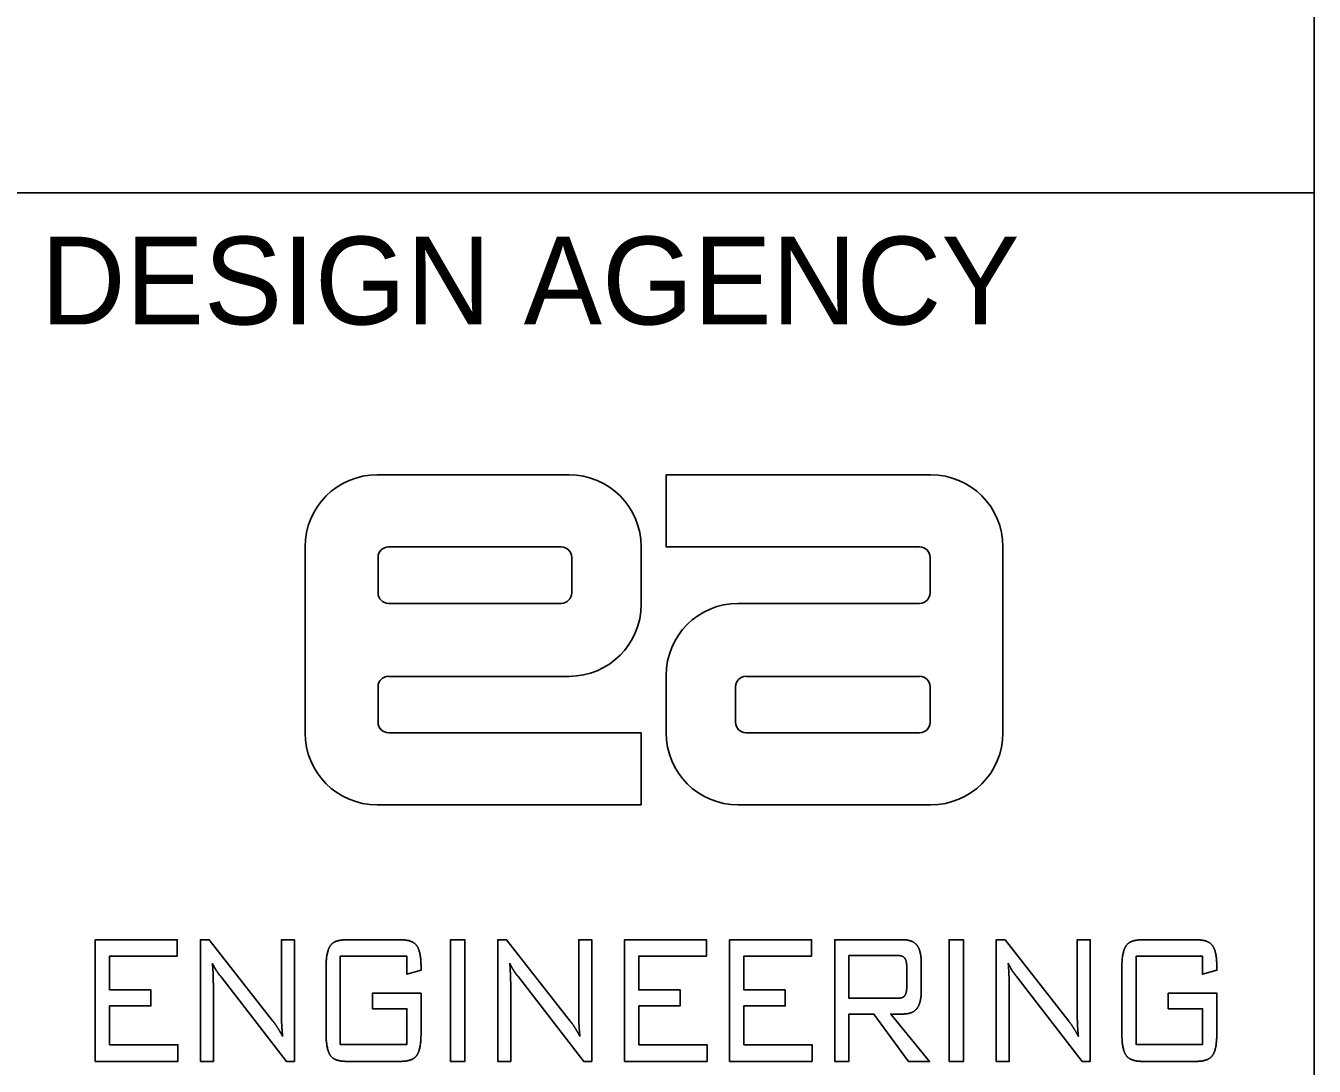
# Model space of a CAD drawing. Extents: x -18.5 to 46, y -14.2 to 42.5.
# Drawn here: x 32.033 to 33.5, y 3.506 to 4.69 of the extents above; entities that cross this region are included whole.
import ezdxf

# ---------------------------------------------------------------- set-up
doc = ezdxf.new("R2010")
doc.units = 0
for name, color, linetype in [('SH_Border', 7, 'Continuous'), ('SH_Data', 7, 'Continuous'), ('TX_X_20', 7, 'Continuous')]:
    doc.layers.add(name, color=color, linetype=linetype)

msp = doc.modelspace()

# ---------------------------------------------------------------- linework, layer by layer
at = {"layer": 'SH_Border'}
msp.add_line((32, 4.5), (33.5, 4.5), dxfattribs=at)
msp.add_lwpolyline([(1.5, 21.5), (33.5, 21.5), (33.5, 0.5), (1.5, 0.5)], close=True, dxfattribs=at)
at = {"layer": 'TX_X_20'}
for p, q in [((32.6515, 4.1788), (32.433, 4.1788)), ((32.433, 4.1788), (32.6515, 4.1788)), ((32.762, 4.1788), (33.0635, 4.1788)), ((32.762, 4.0967), (32.762, 4.1788)), ((32.351, 4.0967), (32.351, 3.8852)), ((32.351, 3.8852), (32.351, 4.0967)), ((32.4459, 4.0967), (32.6426, 4.0967)), ((32.6426, 4.0967), (32.4459, 4.0967)), ((32.7336, 4.0315), (32.7336, 4.0967)), ((32.7336, 4.0967), (32.7336, 4.0315)), ((33.0507, 4.0967), (32.762, 4.0967)), ((33.1456, 3.8852), (33.1456, 4.0967)), ((33.1456, 4.0967), (33.1456, 3.8852)), ((32.434, 4.0444), (32.434, 4.0849)), ((32.434, 4.0849), (32.434, 4.0444)), ((32.6545, 4.0849), (32.6545, 4.0444)), ((32.6545, 4.0444), (32.6545, 4.0849)), ((33.0626, 4.0849), (33.0626, 4.0444)), ((33.0626, 4.0444), (33.0626, 4.0849)), ((32.6426, 4.0325), (32.4459, 4.0325)), ((32.4459, 4.0325), (32.6426, 4.0325)), ((33.0507, 4.0325), (32.8441, 4.0325)), ((32.8441, 4.0325), (33.0507, 4.0325)), ((32.4459, 3.9494), (32.6515, 3.9494)), ((32.6515, 3.9494), (32.4459, 3.9494)), ((32.762, 3.9504), (32.762, 3.8852)), ((32.762, 3.8852), (32.762, 3.9504)), ((32.853, 3.9494), (33.0507, 3.9494)), ((33.0507, 3.9494), (32.853, 3.9494)), ((32.434, 3.8971), (32.434, 3.9376)), ((32.434, 3.9376), (32.434, 3.8971)), ((32.8411, 3.8971), (32.8411, 3.9376)), ((32.8411, 3.9376), (32.8411, 3.8971)), ((33.0626, 3.9376), (33.0626, 3.8971)), ((33.0626, 3.8971), (33.0626, 3.9376)), ((32.4459, 3.8852), (32.7336, 3.8852)), ((32.7336, 3.8852), (32.7336, 3.8031)), ((33.0507, 3.8852), (32.853, 3.8852)), ((32.853, 3.8852), (33.0507, 3.8852)), ((32.7336, 3.8031), (32.433, 3.8031)), ((32.8441, 3.8031), (33.0635, 3.8031)), ((33.0635, 3.8031), (32.8441, 3.8031)), ((32.3975, 3.6495), (32.4602, 3.6495)), ((33.3037, 3.6495), (33.3663, 3.6495)), ((32.3748, 3.5439), (32.3748, 3.6168)), ((33.0361, 3.6173), (33.0361, 3.5971)), ((33.0526, 3.5917), (33.0526, 3.6227)), ((33.2809, 3.5439), (33.2809, 3.6168)), ((32.4602, 3.5111), (32.3975, 3.5111)), ((33.3663, 3.5111), (33.3037, 3.5111))]:
    msp.add_line(p, q, dxfattribs=at)
for points in [[(33.0635, 4.1788), (32.762, 4.1788), (32.762, 4.0967), (33.0507, 4.0967)], [(32.433, 3.8031), (32.7336, 3.8031), (32.7336, 3.8852), (32.4459, 3.8852)], [(32.2465, 3.5927), (32.2465, 3.5111), (32.2317, 3.5111), (32.2317, 3.6495), (32.2419, 3.6495), (32.3144, 3.5569)], [(32.3239, 3.5736), (32.3239, 3.6495), (32.3387, 3.6495), (32.3387, 3.5111), (32.3297, 3.5111), (32.2553, 3.6074)], [(32.5851, 3.5927), (32.5851, 3.5111), (32.5703, 3.5111), (32.5703, 3.6495), (32.5804, 3.6495), (32.6529, 3.5569)], [(32.6625, 3.5736), (32.6625, 3.6495), (32.6773, 3.6495), (32.6773, 3.5111), (32.6682, 3.5111), (32.5938, 3.6074)], [(33.032, 3.6495), (32.954, 3.6495), (32.954, 3.5111), (32.9702, 3.5111), (32.9702, 3.565), (32.9987, 3.565), (33.0381, 3.5111), (33.0621, 3.5111), (33.0178, 3.565), (33.032, 3.565)], [(33.1527, 3.5927), (33.1527, 3.5111), (33.1379, 3.5111), (33.1379, 3.6495), (33.148, 3.6495), (33.2205, 3.5569)], [(33.2301, 3.5736), (33.2301, 3.6495), (33.2449, 3.6495), (33.2449, 3.5111), (33.2358, 3.5111), (33.1614, 3.6074)], [(32.483, 3.6183), (32.483, 3.6149), (32.4668, 3.6103), (32.4668, 3.6307), (32.3909, 3.6307), (32.3909, 3.5304), (32.4668, 3.5304), (32.4668, 3.571), (32.4276, 3.571), (32.4276, 3.5886), (32.483, 3.5886), (32.483, 3.5439)], [(33.0257, 3.5829), (32.9702, 3.5829), (32.9702, 3.6316), (33.0257, 3.6316)], [(33.3891, 3.6183), (33.3891, 3.6149), (33.3729, 3.6103), (33.3729, 3.6307), (33.2971, 3.6307), (33.2971, 3.5304), (33.3729, 3.5304), (33.3729, 3.571), (33.3338, 3.571), (33.3338, 3.5886), (33.3891, 3.5886), (33.3891, 3.5439)]]:
    msp.add_lwpolyline(points, dxfattribs=at)
for points in [[(32.1121, 3.5111), (32.1121, 3.6495), (32.2053, 3.6495), (32.2053, 3.631), (32.1283, 3.631), (32.1283, 3.5925), (32.1754, 3.5925), (32.1754, 3.5742), (32.1283, 3.5742), (32.1283, 3.5301), (32.2061, 3.5301), (32.2061, 3.5111)], [(32.5166, 3.5111), (32.5166, 3.6495), (32.5329, 3.6495), (32.5329, 3.5111)], [(32.7147, 3.5111), (32.7147, 3.6495), (32.8079, 3.6495), (32.8079, 3.631), (32.7309, 3.631), (32.7309, 3.5925), (32.778, 3.5925), (32.778, 3.5742), (32.7309, 3.5742), (32.7309, 3.5301), (32.8087, 3.5301), (32.8087, 3.5111)], [(32.8343, 3.5111), (32.8343, 3.6495), (32.9276, 3.6495), (32.9276, 3.631), (32.8506, 3.631), (32.8506, 3.5925), (32.8977, 3.5925), (32.8977, 3.5742), (32.8506, 3.5742), (32.8506, 3.5301), (32.9283, 3.5301), (32.9283, 3.5111)], [(33.0842, 3.5111), (33.0842, 3.6495), (33.1005, 3.6495), (33.1005, 3.5111)]]:
    msp.add_lwpolyline(points, close=True, dxfattribs=at)
for centre, radius, start, end in [((32.433, 4.0967), 0.0821, 90, 180), ((32.433, 4.0967), 0.0821, 90, 180), ((32.6515, 4.0967), 0.0821, 0, 90), ((32.6515, 4.0967), 0.0821, 0, 90), ((33.0635, 4.0967), 0.0821, 0, 90), ((33.0635, 4.0967), 0.0821, 0, 90), ((32.4459, 4.0849), 0.0119, 90, 180), ((32.4459, 4.0849), 0.0119, 90, 180), ((32.6426, 4.0849), 0.0119, 0, 90), ((32.6426, 4.0849), 0.0119, 0, 90), ((33.0507, 4.0849), 0.0119, 0, 90), ((33.0507, 4.0849), 0.0119, 0, 90), ((32.4459, 4.0444), 0.0119, 180, 270), ((32.4459, 4.0444), 0.0119, 180, 270), ((32.6426, 4.0444), 0.0119, 270, 0), ((32.6426, 4.0444), 0.0119, 270, 0), ((33.0507, 4.0444), 0.0119, 270, 0), ((33.0507, 4.0444), 0.0119, 270, 0), ((32.6515, 4.0315), 0.0821, 270, 360), ((32.6515, 4.0315), 0.0821, 270, 360), ((32.8441, 3.9504), 0.0821, 90, 180), ((32.8441, 3.9504), 0.0821, 90, 180), ((32.4459, 3.9376), 0.0119, 90, 180), ((32.4459, 3.9376), 0.0119, 90, 180), ((32.853, 3.9376), 0.0119, 90, 180), ((32.853, 3.9376), 0.0119, 90, 180), ((33.0507, 3.9376), 0.0119, 0, 90), ((33.0507, 3.9376), 0.0119, 0, 90), ((32.4459, 3.8971), 0.0119, 180, 270), ((32.4459, 3.8971), 0.0119, 180, 270), ((32.853, 3.8971), 0.0119, 180, 270), ((32.853, 3.8971), 0.0119, 180, 270), ((33.0507, 3.8971), 0.0119, 270, 0), ((33.0507, 3.8971), 0.0119, 270, 0), ((32.433, 3.8852), 0.0821, 180, 270), ((32.433, 3.8852), 0.0821, 180, 270), ((32.8441, 3.8852), 0.0821, 180, 270), ((32.8441, 3.8852), 0.0821, 180, 270), ((33.0635, 3.8852), 0.0821, 270, 360), ((33.0635, 3.8852), 0.0821, 270, 360)]:
    msp.add_arc(centre, radius, start, end, dxfattribs=at)
for points in [[(32.3748, 3.6168), (32.3748, 3.6356), (32.3795, 3.6426)], [(32.3795, 3.6426), (32.3842, 3.6495), (32.3975, 3.6495)], [(32.4602, 3.6495), (32.4732, 3.6495), (32.4781, 3.6428)], [(32.4781, 3.6428), (32.483, 3.636), (32.483, 3.6183)], [(33.0477, 3.6432), (33.0429, 3.6495), (33.032, 3.6495)], [(33.0526, 3.6227), (33.0526, 3.6368), (33.0477, 3.6432)], [(33.2809, 3.6168), (33.2809, 3.6356), (33.2857, 3.6426)], [(33.2857, 3.6426), (33.2904, 3.6495), (33.3037, 3.6495)], [(33.3663, 3.6495), (33.3794, 3.6495), (33.3842, 3.6428)], [(33.3842, 3.6428), (33.3891, 3.636), (33.3891, 3.6183)], [(33.0257, 3.6316), (33.0316, 3.6316), (33.0339, 3.6284)], [(33.0339, 3.6284), (33.0361, 3.6252), (33.0361, 3.6173)], [(32.2536, 3.6094), (32.2481, 3.6165), (32.2454, 3.6229)], [(32.2454, 3.6229), (32.246, 3.6166), (32.2463, 3.6095)], [(32.2463, 3.6095), (32.2465, 3.6024), (32.2465, 3.5927)], [(32.2553, 3.6074), (32.2547, 3.608), (32.2536, 3.6094)], [(32.5921, 3.6094), (32.5866, 3.6165), (32.584, 3.6229)], [(32.584, 3.6229), (32.5845, 3.6166), (32.5848, 3.6095)], [(32.5848, 3.6095), (32.5851, 3.6024), (32.5851, 3.5927)], [(32.5938, 3.6074), (32.5932, 3.608), (32.5921, 3.6094)], [(33.1597, 3.6094), (33.1542, 3.6165), (33.1516, 3.6229)], [(33.1516, 3.6229), (33.1521, 3.6166), (33.1524, 3.6095)], [(33.1524, 3.6095), (33.1527, 3.6024), (33.1527, 3.5927)], [(33.1614, 3.6074), (33.1608, 3.608), (33.1597, 3.6094)], [(33.0361, 3.5971), (33.0361, 3.5892), (33.0339, 3.5861)], [(33.0339, 3.5861), (33.0317, 3.5829), (33.0257, 3.5829)], [(33.0477, 3.5714), (33.0526, 3.5777), (33.0526, 3.5917)], [(32.3243, 3.5535), (32.3239, 3.5607), (32.3239, 3.5736)], [(32.6628, 3.5535), (32.6625, 3.5607), (32.6625, 3.5736)], [(33.032, 3.565), (33.0429, 3.565), (33.0477, 3.5714)], [(33.2304, 3.5535), (33.2301, 3.5607), (33.2301, 3.5736)], [(32.3144, 3.5569), (32.3169, 3.5538), (32.3197, 3.5493)], [(32.3254, 3.5395), (32.3247, 3.5462), (32.3243, 3.5535)], [(32.6529, 3.5569), (32.6554, 3.5538), (32.6582, 3.5493)], [(32.6639, 3.5395), (32.6632, 3.5462), (32.6628, 3.5535)], [(33.2205, 3.5569), (33.223, 3.5538), (33.2258, 3.5493)], [(33.2315, 3.5395), (33.2308, 3.5462), (33.2304, 3.5535)], [(32.3197, 3.5493), (32.3225, 3.5449), (32.3254, 3.5395)], [(32.3795, 3.5181), (32.3748, 3.525), (32.3748, 3.5439)], [(32.483, 3.5439), (32.483, 3.5249), (32.4782, 3.518)], [(32.6582, 3.5493), (32.661, 3.5449), (32.6639, 3.5395)], [(33.2258, 3.5493), (33.2286, 3.5449), (33.2315, 3.5395)], [(33.2857, 3.5181), (33.2809, 3.525), (33.2809, 3.5439)], [(33.3891, 3.5439), (33.3891, 3.5249), (33.3843, 3.518)], [(32.3975, 3.5111), (32.3842, 3.5111), (32.3795, 3.5181)], [(32.4782, 3.518), (32.4734, 3.5111), (32.4602, 3.5111)], [(33.3037, 3.5111), (33.2904, 3.5111), (33.2857, 3.5181)], [(33.3843, 3.518), (33.3795, 3.5111), (33.3663, 3.5111)]]:
    msp.add_open_spline(points, degree=2, dxfattribs=at)

# ---------------------------------------------------------------- texts
at = {"layer": 'SH_Data'}
msp.add_text('DESIGN AGENCY', height=0.1, dxfattribs=at).set_placement((32.05, 4.35))

doc.saveas('drawing.dxf')
